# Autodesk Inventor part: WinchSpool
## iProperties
Author: Administrator
Shininess: 20.0
PropertySet Name: _Private Model Information
Created: 2001-04
Part Number: WinchSpool
Document SubType Name: Modeling
Designer: Administrator
Control State: 0
Master: False
Checked Out: False
PropertySet Name: Design Tracking Control
Density: 0.0
Volumn: 0.0
Area: 0.0
PropertySet Name: Model Information
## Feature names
1. Revolution1
